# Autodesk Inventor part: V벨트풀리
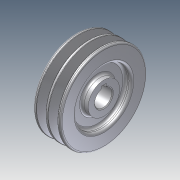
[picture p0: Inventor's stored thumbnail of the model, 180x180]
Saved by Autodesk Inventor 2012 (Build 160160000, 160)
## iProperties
Company: 한국ATC센터
Created: 2015-02
Part Number: V벨트풀리
Document SubType Name: Modeling
Designer: KYOUNG IL JANG
Density: 1 g/cm^3
Material: 기본값
Author: KYOUNG IL JANG
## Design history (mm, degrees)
sketch "스케치1"
  geometry: L1 (0, 0)-(35, 0); L2 (35, 0)-(35, 55); L3 (35, 55)-(31.062, 55); L4 (31.062, 55)-(27.001, 42.5); L5 (27.001, 42.5)-(22.999, 42.5); L6 (22.999, 42.5)-(18.938, 55); L7 (18.938, 55)-(16.062, 55); L8 (16.062, 55)-(12.001, 42.5); L9 (12.001, 42.5)-(7.999, 42.5); L10 (7.999, 42.5)-(3.938, 55); L11 (3.938, 55)-(0, 55); L12 (0, 55)-(0, 0); L13 (5.4, 50.5)-(14.6, 50.5); L14 (20.4, 50.5)-(29.6, 50.5); 3 further points
  constraints: 28 end point, 8 parallel, 6 collinear, 4 point on line, 3 midpoint, 2 perpendicular, 1 horizontal, 1 vertical alignment
  dimensions: "d0" = 36 deg angle of L8 L10; "d1" = 9.2 distance of L14.start L14.end; "d2" = 4.5 distance between parallel lines of L13 L11; "d3" = 8 distance between parallel lines of L9 L13; "d4" = 10 distance from line of point (25, 42.5) L2; "d5" = 15 distance of point (25, 42.5) point (10, 42.5); "d6" = 35 distance of L1.start L1.end; "d7" = 101 diameter of L14 L1
revolve "회전1" sketch "스케치1" stored, may be unused: angle "d8" = 90 deg
fillet "모깎기1" dims "d9" = 2
fillet "모깎기2" dims "d10" = 0.5
fillet "모깎기3" dims "d11" = 1
sketch "스케치2"
  geometry: L1 (0, 0)-(8, 0); L2 (8, 0)-(8, 20); L3 (8, 20)-(17, 20); L4 (17, 20)-(17, 35); L5 (17, 35)-(0, 35); L6 (0, 35)-(0, 0); L7 (35, 35)-(27, 35); L8 (27, 35)-(27, 20); L9 (27, 20)-(35, 20); L10 (35, 20)-(35, 35); L11 (35, 53)-(35, -53) reference
  constraints: 20 end point, 6 parallel, 3 collinear, 3 perpendicular, 1 horizontal
  dimensions: "d12" = 40 diameter of L9 L1; "d13" = 70 diameter of L7 L1; "d14" = 8 distance between parallel lines of L10 L8; "d15" = 10 distance between parallel lines of L8 L4; "d16" = 9 distance between parallel lines of L4 L2
revolve "회전2" sketch "스케치2" stored, may be unused: angle "d17" = 90 deg
hole "구멍1" diameter "d20" = 22; stored, may be unused: countersink angle "d24" = 90 deg, drill point angle "d26" = 118 deg; dims "d18" = 10, "d19" = 10, "d21" = 6, "d22" = 4, "d23" = 2, "d25" = 8
sketch "스케치3"
  geometry: L1 (-14.8, -3)-(-7.8, -3); L2 (-7.8, -3)-(-7.8, 3); L3 (-7.8, 3)-(-14.8, 3); L4 (-14.8, 3)-(-14.8, -3); C1 r 11 at (0, 0) reference; 2 further points
  constraints: 8 end point, 2 parallel, 1 horizontal, 1 horizontal alignment, 1 midpoint, 1 perpendicular
  dimensions: "d27" = 25.8 dimension on C1 L4; "d28" = 6 distance of L3.end L1.start; "d29" = 7 distance between parallel lines of L4 L2
extrude "돌출1" cut sketch "스케치3" stored distance "d30" = 10; taper "d31" = 0 deg
fillet "모깎기4" dims "d32" = 3
chamfer "모따기1" distance "d33" = 1; stored, may be unused: second distance "d34" = 2, angle "d35" = 45 deg
node "솔리드1"
